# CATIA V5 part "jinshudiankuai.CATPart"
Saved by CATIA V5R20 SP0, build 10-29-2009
Part number: 金属垫块
Material "Steel": density 7860 kg/m3, Young's modulus 2e+11 Pa, Poisson ratio 0.266, thermal expansion 1.17e-05 1/K
Bounding box of the stored display mesh (mm): x -35 to 35, y -25 to 25, z -10 to 10
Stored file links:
  F:\CATIA\XLW\jinshudiankuai.CATPart
  D:\CATIA\intel_a\startup\materials\Catalog.CATMaterial
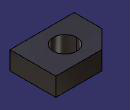
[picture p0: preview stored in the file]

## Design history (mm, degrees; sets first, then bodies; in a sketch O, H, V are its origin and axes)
Body1 (main body), material "Steel"
  Sketch1 on xy-plane, origin (0, 0, 0), H (1, 0, 0), V (0, 1, 0)
    line L1 (35, 25) -> (35, -25)
    line L2 (35, -25) -> (-35, -25)
    line L3 (-35, -25) -> (-35, 5)
    line L4 (-15, 25) -> (35, 25)
    line L5 (-35, 5) -> (-15, 25)
    circle A1 centre (0, 0) radius 13
    length L4 = 50
    length L1 = 50
    length L2 = 70
    length L3 = 30
    radius A1 = 13
    vertical: L1 V, L3 V
    horizontal: L2 H, L4 H
    equidistance: L1 L3 O, L2 L4 O
  Pad1: profile Sketch1, direction (0, 0, 1), length 10, mirrored extent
